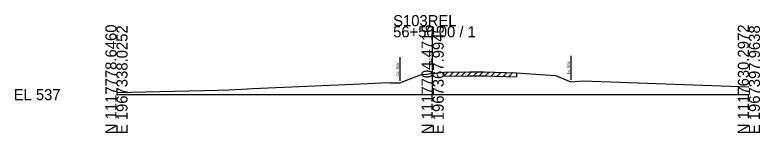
# Model space of a CAD drawing. Extents: x -26 to 163, y -10 to 24518.
# Drawn here: x -25.7 to 162.8, y 6990.3 to 7020.1 of the extents above; entities that cross this region are included whole.
import ezdxf

# ---------------------------------------------------------------- set-up
doc = ezdxf.new("R2010")
doc.units = 0
for name, color, linetype in [('RD_GPK_XS_Cell', 7, 'Continuous'), ('RD_XS_ExGround', 7, 'Continuous'), ('RD_XS_ExPaveRet', 7, 'Continuous'), ('RD_XS_ExRW', 7, 'Continuous'), ('RD_XS_TX_Elev_EX', 7, 'Continuous')]:
    doc.layers.add(name, color=color, linetype=linetype)

msp = doc.modelspace()

# ---------------------------------------------------------------- linework, layer by layer
at = {"layer": 'RD_GPK_XS_Cell'}
for p, q in [((80, 7000), (80, 7017.25)), ((0, 7000), (80, 7000)), ((80, 7000), (160, 7000))]:
    msp.add_line(p, q, dxfattribs=at)
at = {"layer": 'RD_XS_ExGround'}
msp.add_lwpolyline([(0, 7000.56), (25.66, 7001.12), (28.48, 7001.24), (31.63, 7001.38), (34.49, 7001.55), (61.79, 7002.72), (68.72, 7003.02), (69.32, 7003.01), (71.73, 7002.95), (73.61, 7003.74), (76.94, 7005.03), (79.03, 7005.25), (80, 7005.35), (82.8, 7005.64), (89.38, 7005.73), (91.31, 7005.75), (93.07, 7005.71), (101.2, 7005.52), (109.71, 7004.9), (111.05, 7004.81), (114.97, 7003.24), (118.01, 7003.49), (160, 7001.94)], dxfattribs=at)
at = {"layer": 'RD_XS_ExPaveRet'}
for p, q in [((82.8, 7004.64), (83.81, 7005.66)), ((82.8, 7004.64), (82.8, 7005.64)), ((82.8, 7004.64), (89.38, 7004.73)), ((84.3, 7004.66), (85.31, 7005.68)), ((85.8, 7004.68), (86.81, 7005.7)), ((87.3, 7004.7), (88.31, 7005.72)), ((88.8, 7004.72), (89.81, 7005.73)), ((89.38, 7004.73), (91.31, 7004.75)), ((90.3, 7004.74), (91.31, 7005.75)), ((91.31, 7004.75), (93.07, 7004.71)), ((91.8, 7004.74), (92.78, 7005.72)), ((93.07, 7004.71), (101.2, 7004.52)), ((93.3, 7004.71), (94.27, 7005.68)), ((94.8, 7004.67), (95.77, 7005.65)), ((96.3, 7004.64), (97.27, 7005.61)), ((97.8, 7004.6), (98.77, 7005.58)), ((99.3, 7004.57), (100.27, 7005.54)), ((101.2, 7005.52), (101.2, 7004.52))]:
    msp.add_line(p, q, dxfattribs=at)
at = {"layer": 'RD_XS_ExRW'}
for p, q in [((114.97, 7009.74), (114.97, 7003.74)), ((114.97, 7009.74), (114.97, 7003.74)), ((71.73, 7009.45), (71.73, 7003.45))]:
    msp.add_line(p, q, dxfattribs=at)

# ---------------------------------------------------------------- texts
at = {"layer": 'RD_GPK_XS_Cell'}
for s, p in [('S103REL', (70, 7017.25)), ('56+50.00 / 1', (70, 7014.45)), ('EL 537', (-26, 6998.6))]:
    msp.add_text(s, height=2.8, dxfattribs=at).set_placement(p)
for s, p in [('N 1117778.6460', (0, 6990)), ('E 1967338.0252', (2.8, 6990)), ('N 1117704.4716', (80, 6990)), ('E 1967367.9945', (82.8, 6990)), ('N 1117630.2972', (160, 6990)), ('E 1967397.9638', (162.8, 6990))]:
    msp.add_text(s, height=2.8, rotation=90, dxfattribs=at).set_placement(p)
at = {"layer": 'RD_XS_ExRW'}
for p in [(71.48, 7004.8), (114.72, 7005.09), (114.72, 7005.09)]:
    msp.add_text('Ex. R/W ', height=0.65, rotation=90, dxfattribs=at).set_placement(p)
at = {"layer": 'RD_XS_TX_Elev_EX'}
msp.add_text('542.35', height=0.8, rotation=90, dxfattribs=at).set_placement((79.9, 7007.35))

doc.saveas('drawing.dxf')
